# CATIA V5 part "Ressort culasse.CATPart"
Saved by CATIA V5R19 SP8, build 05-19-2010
Part number: Ressort culasse
Bounding box of the stored display mesh (mm): x -4 to 4, y -4 to 4, z -0.15 to 69.15
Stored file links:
  C:\Users\Arthur\Desktop\Catia parts\GLOCK\Ensemble culasse\Ressort culasse.CATPart
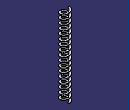
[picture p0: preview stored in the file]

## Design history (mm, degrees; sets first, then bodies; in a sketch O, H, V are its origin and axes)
Set1
  Sketch1 on yz-plane, origin (0, 0, 0), H (0, 1, 0), V (0, 0, 1)
    point P1 (3.25, 0)
    axis line L1 (2.5, 0) -> (2.5, -10)
    point P2 (2.5, 0)
    distance L1 V = 2.5
    distance P1 P2 = 0.75
    vertical: L1 V
  Plane1: type OffsetPt, RefPlane yz-plane, RefPoint Sketch1
Body1 (main body)
  Helix1: Direction Sketch1.V, RefPoint Sketch1, Pitch 4, Height 69, TaperAngle 0
  Sketch2 on Plane1, origin (0, 0, 0), H (0, 1, 0), V (0, 0, 1)
    point P1 (3.25, 0)
    line L1 (4, 0.15) -> (4, -0.15)
    line L2 (4, -0.15) -> (2.5, -0.15)
    line L3 (2.5, -0.15) -> (2.5, 0.15)
    line L4 (2.5, 0.15) -> (4, 0.15)
    reference projected point E1 (3.25, 0) from Sketch1
    length L1 = 0.3
    length L2 = 1.5
    vertical: L1 V, L3 V
    horizontal: L2 H, L4 H
    equidistance: L1 L3 P1, L2 L4 P1
    coincidence: P1 E1
  Rib1: profile Sketch2, centre curve Helix1
  Plane2: type Offset, RefPlane xy-plane, Offset 0.15, reversed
